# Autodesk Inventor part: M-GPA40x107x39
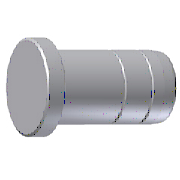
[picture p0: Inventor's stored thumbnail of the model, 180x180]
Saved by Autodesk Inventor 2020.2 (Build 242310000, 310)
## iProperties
Manager: www.cadconsulting.pl
Company: Fabian Stasiak CAD Consulting
Created: 2014-02
Part Number: M-GPA40x107x39
Material: SUJ 2
Description: GUIDE PIN
Document SubType Name: Modeling
Designer: F.Stasiak
Standard Revision: 1
Manufacturer: FUTABA
Language: pl-PL
Size Designation: 40x107x39
Categories: <MemberInstance><Categories><Category DisplayName="Forma wtryskowa" InternalName="349578f2-f4d4-4954-8c09-8e99297a61c0" Mnemonic="MOLD"><Category DisplayName="K
Mass: 12.6115 g
Surface Area: 36.5267 cm^2
Volume: 12.6115 cm^3
Density: 7.85 g/cm^3
Appearance: Domyślna
Catalog Web Link: www.expertbooks.pl
IsCustomPart: 0
Author: F.Stasiak
Subject: Zbiór ćwiczeń. Autodesk Inventor 2020. Kurs Professional
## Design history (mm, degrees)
sketch "Sketch1"
  geometry: L1 (0, -114.465)-(0, 26.077) reference; L2 (0, 10)-(22.5, 10); L3 (22.5, 10)-(22.5, 0); L4 (22.5, 0)-(19.5, 0); L5 (19.5, 0)-(19.5, -1.5); L6 (19.5, -1.5)-(20, -1.5); L7 (20, -1.5)-(20, -29); L8 (20, -29)-(20, -29); L9 (20, -29)-(20, -89); L10 (20, -89)-(19.46, -95.174); L11 (17.467, -97)-(0, -97); L12 (0, 10)-(0, -97); A1 r 2 centre (17.467, -95) between (17.467, -97) and (19.46, -95.174); 2 further points
  constraints: 30 end point, 5 perpendicular, 4 parallel, 4 point on line, 2 point on circle, 2 tangent, 1 centre point, 1 collinear, 1 horizontal alignment
  dimensions: "d0" = 45 diameter of L3 L1 (= D); "d2" = 1.5 distance of L4.end L5.end; "d3" = 10 distance between parallel lines of L4 L2 (= H_); "d5" = 0.5 distance between parallel lines of L7 L5; "d6" = 39 distance between parallel lines of L2 L8 (= N_); "d7" = 40 diameter of L7 L1 (= d1); "d8" = 107 distance between parallel lines of L2 L11 (= L); "d9" = 40 diameter of L9 L1 (= d_); "d10" = 8 vertical distance of L9.end point (19.3, -97) (= E_); "d11" = 5 deg angle of L9 L10; "d12" = 2 radius of A1
revolve "Revolution1" sketch "Sketch1" stored, may be unused: angle "d18" = 90 deg
sketch "Sketch2"
  geometry: L1 (20, -1.5)-(20, -89) reference; C1 r 0.5 at (20, -17.667)
  constraints: 1 centre point, 1 point on line
  dimensions: "d31" = 1 diameter of C1; "d68" = 71.33333 distance of L1.end C1.centre (derived)
coil "Coil1" sketch "Sketch2" pitch "d37" = 22.66667 (= P); turns "d39" = 3; dims "d38" = 53.5 (derived), "d40" = 0, angle "d41" = 90 deg, angle "d42" = 90 deg, "d43" = 0, "d44" = 0
sketch "Sketch3"
  geometry: L1 (0.5, 0)-(-0.5, 0); A1 r 0.5 centre (0, 0) between (-0.5, 0) and (0.5, 0) reference; A2 r 0.5 centre (0, 0) between (-0.5, 0) and (0.5, 0)
  constraints: 2 end point, 2 point on circle, 1 centre point, 1 coincident, 1 horizontal, 1 midpoint
  dimensions: "d71" = 0.5 radius of A2
revolve "Revolution2" sketch "Sketch3" stored, may be unused: angle "d54" = 90 deg
sketch "Sketch4"
  geometry: L1 (-0.5, 0)-(0.5, 0); A1 r 0.5 centre (0, 0) between (-0.5, 0) and (0.5, 0) reference; A2 r 0.5 centre (0, 0) between (-0.5, 0) and (0.5, 0)
  constraints: 2 end point, 2 point on circle, 1 centre point, 1 coincident, 1 horizontal, 1 midpoint
  dimensions: "d72" = 0.5 radius of A2
revolve "Revolution3" sketch "Sketch4" stored, may be unused: angle "d55" = 90 deg
sketch "Sketch5"
  geometry: L1 (20, -1.5)-(20, -89) reference; L2 (0, -106.8)-(0, 17.8) reference; C1 r 0.5 at (20, -26.583); C2 r 0.5 at (20, -62.25); 1 further point
  constraints: 2 centre point, 2 point on line, 1 equal radius
  dimensions: "d59" = 1 diameter of C1; "d61" = 35.66667 distance of C2.centre C1.centre (derived); "d69" = 26.75 distance of L1.end C2.centre (derived)
revolve "Revolution4" sketch "Sketch5" stored, may be unused: angle "d70" = 90 deg
fillet "Fillet1" dims "d63" = 0.3
chamfer "Chamfer1" distance "d64" = 0.5; stored, may be unused: second distance "d65" = 2, angle "d66" = 45 deg
body "Solid1"
other parameters: "d_" = 40 [user parameter; used in 1 equation term], "L" = 107 [user parameter; used in 1 equation term], "d1" = 40 [user parameter; used in 1 equation term], "H_" = 10 [user parameter; used in 1 equation term], "D" = 45 [user parameter; used in 1 equation term], "N_" = 39 [user parameter; used in 1 equation term], "S_" = 45.33333 [user parameter], "P" = 22.66667 [user parameter; used in 1 equation term], "d56" = 0, "d58" = 0, "E_" = 8 [user parameter; used in 1 equation term], "d67" = 0
